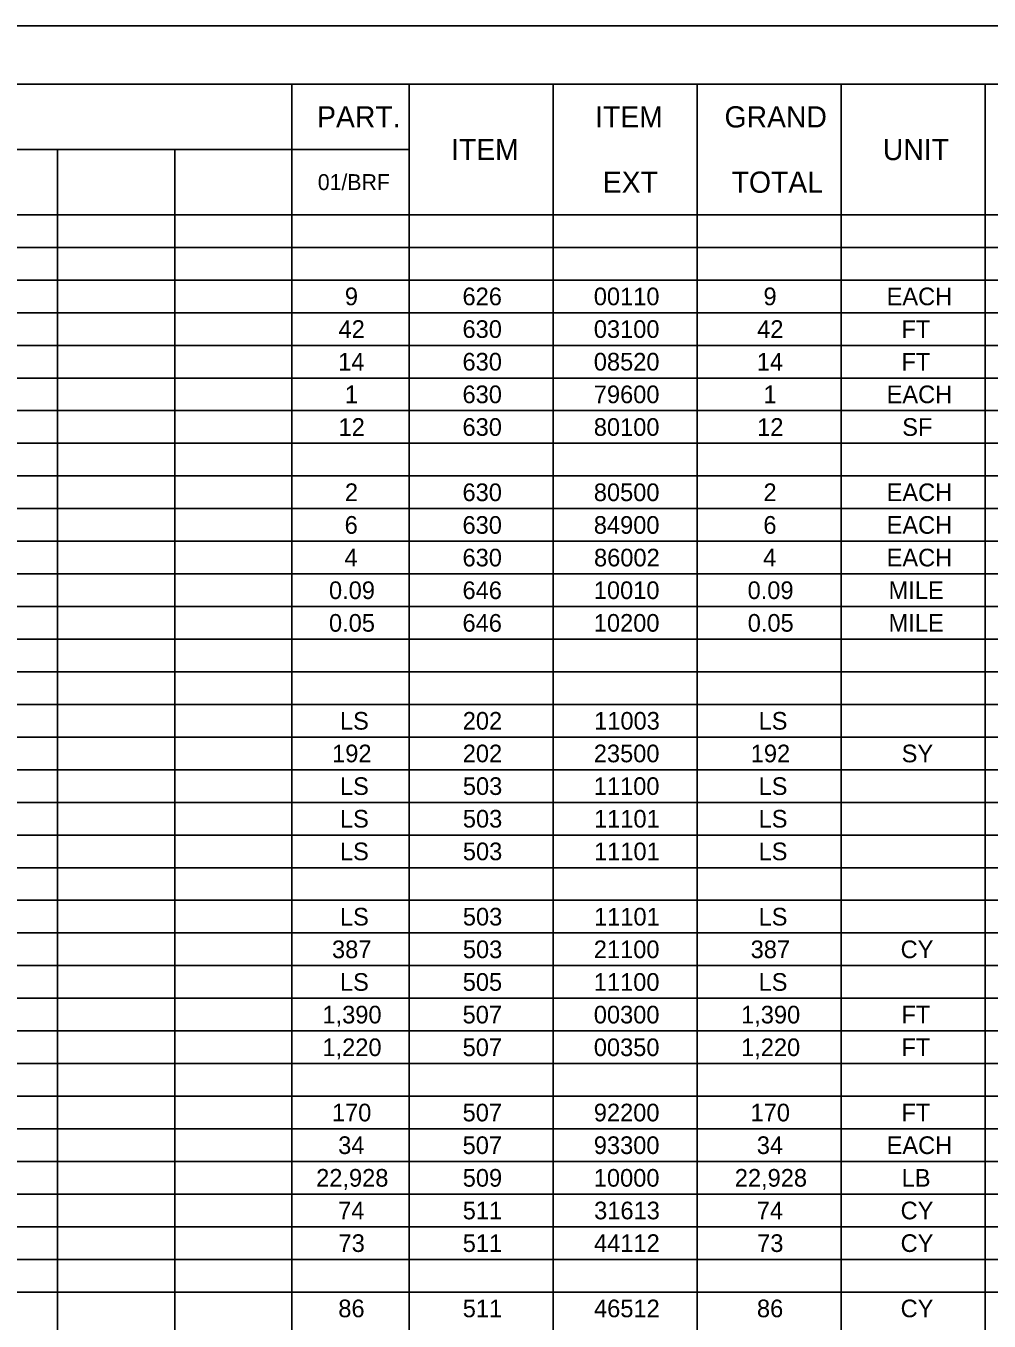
# Model space of a CAD drawing. Extents: x 0 to 34, y 0 to 22.
# Drawn here: x 8.26 to 16.52, y 10.89 to 22 of the extents above; entities that cross this region are included whole.
import ezdxf

# ---------------------------------------------------------------- set-up
doc = ezdxf.new("R2010")
doc.units = 0
for name, color, linetype in [('SH_Border', 7, 'Continuous'), ('SH_Cut_Line', 7, 'Continuous'), ('SH_Text', 7, 'Continuous')]:
    doc.layers.add(name, color=color, linetype=linetype)

msp = doc.modelspace()

# ---------------------------------------------------------------- linework, layer by layer
at = {"layer": 'SH_Border'}
msp.add_lwpolyline([(1.5, 21.5), (33.5, 21.5), (33.5, 0.5), (1.5, 0.5)], close=True, dxfattribs=at)
at = {"layer": 'SH_Cut_Line'}
msp.add_lwpolyline([(0, 0), (34, 0), (34, 22), (0, 22)], close=True, dxfattribs=at)
at = {"layer": 'SH_Text'}
for p, q in [((1.5, 21.5), (32, 21.5)), ((10.541, 21.5), (10.541, 0.5)), ((11.546, 21.5), (11.546, 0.5)), ((12.781, 21.5), (12.781, 0.5)), ((14.016, 21.5), (14.016, 0.5)), ((15.251, 21.5), (15.251, 0.5)), ((16.487, 21.5), (16.487, 0.5)), ((1.5, 20.94), (11.546, 20.94)), ((8.532, 20.94), (8.532, 0.5)), ((9.537, 20.94), (9.537, 0.5)), ((1.5, 20.38), (32, 20.38)), ((1.5, 20.1), (32, 20.1)), ((1.5, 19.82), (32, 19.82)), ((1.5, 19.54), (32, 19.54)), ((1.5, 19.26), (32, 19.26)), ((1.5, 18.98), (32, 18.98)), ((1.5, 18.7), (32, 18.7)), ((1.5, 18.42), (32, 18.42)), ((1.5, 18.14), (32, 18.14)), ((1.5, 17.86), (32, 17.86)), ((1.5, 17.58), (32, 17.58)), ((1.5, 17.3), (32, 17.3)), ((1.5, 17.02), (32, 17.02)), ((1.5, 16.74), (32, 16.74)), ((1.5, 16.46), (32, 16.46)), ((1.5, 16.18), (32, 16.18)), ((1.5, 15.9), (32, 15.9)), ((1.5, 15.62), (32, 15.62)), ((1.5, 15.34), (32, 15.34)), ((1.5, 15.06), (32, 15.06)), ((1.5, 14.78), (32, 14.78)), ((1.5, 14.5), (32, 14.5)), ((1.5, 14.22), (32, 14.22)), ((1.5, 13.94), (32, 13.94)), ((1.5, 13.66), (32, 13.66)), ((1.5, 13.38), (32, 13.38)), ((1.5, 13.1), (32, 13.1)), ((1.5, 12.82), (32, 12.82)), ((1.5, 12.54), (32, 12.54)), ((1.5, 12.26), (32, 12.26)), ((1.5, 11.98), (32, 11.98)), ((1.5, 11.7), (32, 11.7)), ((1.5, 11.42), (32, 11.42)), ((1.5, 11.14), (32, 11.14))]:
    msp.add_line(p, q, dxfattribs=at)

# ---------------------------------------------------------------- texts
for s, height, p in [('PART.', 0.1818, (10.757, 21.129)), ('ITEM', 0.1818, (13.141, 21.129)), ('GRAND', 0.1818, (14.251, 21.129)), ('ITEM', 0.1818, (11.906, 20.849)), ('UNIT', 0.1818, (15.609, 20.849)), ('01/BRF', 0.1364, (10.763, 20.592)), ('EXT', 0.1818, (13.207, 20.569)), ('TOTAL', 0.1818, (14.312, 20.569)), ('9', 0.152, (10.995, 19.604)), ('626', 0.1515, (12.004, 19.604)), ('00110', 0.1515, (13.13, 19.604)), ('9', 0.152, (14.585, 19.604)), ('EACH', 0.1515, (15.641, 19.604)), ('42', 0.1515, (10.941, 19.324)), ('630', 0.1515, (12.004, 19.324)), ('03100', 0.1515, (13.13, 19.324)), ('42', 0.1515, (14.531, 19.324)), ('FT', 0.1515, (15.768, 19.324)), ('14', 0.1515, (10.938, 19.044)), ('630', 0.1515, (12.004, 19.044)), ('08520', 0.1515, (13.13, 19.044)), ('14', 0.1515, (14.528, 19.044)), ('FT', 0.1515, (15.768, 19.044)), ('1', 0.152, (10.995, 18.764)), ('630', 0.1515, (12.004, 18.764)), ('79600', 0.1515, (13.13, 18.764)), ('1', 0.152, (14.585, 18.764)), ('EACH', 0.1515, (15.641, 18.764)), ('12', 0.1515, (10.941, 18.484)), ('630', 0.1515, (12.004, 18.484)), ('80100', 0.1515, (13.13, 18.484)), ('12', 0.1515, (14.531, 18.484)), ('SF', 0.1515, (15.775, 18.484)), ('2', 0.152, (10.995, 17.924)), ('630', 0.1515, (12.004, 17.924)), ('80500', 0.1515, (13.13, 17.924)), ('2', 0.152, (14.585, 17.924)), ('EACH', 0.1515, (15.641, 17.924)), ('6', 0.152, (10.993, 17.644)), ('630', 0.1515, (12.004, 17.644)), ('84900', 0.1515, (13.13, 17.644)), ('6', 0.152, (14.584, 17.644)), ('EACH', 0.1515, (15.641, 17.644)), ('4', 0.152, (10.992, 17.364)), ('630', 0.1515, (12.004, 17.364)), ('86002', 0.1515, (13.132, 17.364)), ('4', 0.152, (14.582, 17.364)), ('EACH', 0.1515, (15.641, 17.364)), ('0.09', 0.1515, (10.859, 17.084)), ('646', 0.1515, (12.004, 17.084)), ('10010', 0.1515, (13.13, 17.084)), ('0.09', 0.1515, (14.449, 17.084)), ('MILE', 0.1515, (15.658, 17.084)), ('0.05', 0.1515, (10.859, 16.804)), ('646', 0.1515, (12.004, 16.804)), ('10200', 0.1515, (13.13, 16.804)), ('0.05', 0.1515, (14.45, 16.804)), ('MILE', 0.1515, (15.658, 16.804)), ('LS', 0.1515, (10.953, 15.964)), ('202', 0.1515, (12.006, 15.964)), ('11003', 0.1515, (13.133, 15.964)), ('LS', 0.1515, (14.543, 15.964)), ('192', 0.1515, (10.886, 15.684)), ('202', 0.1515, (12.006, 15.684)), ('23500', 0.1515, (13.13, 15.684)), ('192', 0.1515, (14.476, 15.684)), ('SY', 0.1515, (15.77, 15.684)), ('LS', 0.1515, (10.953, 15.404)), ('503', 0.1515, (12.007, 15.404)), ('11100', 0.1515, (13.13, 15.404)), ('LS', 0.1515, (14.543, 15.404)), ('LS', 0.1515, (10.953, 15.124)), ('503', 0.1515, (12.007, 15.124)), ('11101', 0.1515, (13.132, 15.124)), ('LS', 0.1515, (14.543, 15.124)), ('LS', 0.1515, (10.953, 14.844)), ('503', 0.1515, (12.007, 14.844)), ('11101', 0.1515, (13.132, 14.844)), ('LS', 0.1515, (14.543, 14.844)), ('LS', 0.1515, (10.953, 14.284)), ('503', 0.1515, (12.007, 14.284)), ('11101', 0.1515, (13.132, 14.284)), ('LS', 0.1515, (14.543, 14.284)), ('387', 0.1515, (10.885, 14.004)), ('503', 0.1515, (12.007, 14.004)), ('21100', 0.1515, (13.13, 14.004)), ('387', 0.1515, (14.475, 14.004)), ('CY', 0.1515, (15.761, 14.004)), ('LS', 0.1515, (10.953, 13.724)), ('505', 0.1515, (12.006, 13.724)), ('11100', 0.1515, (13.13, 13.724)), ('LS', 0.1515, (14.543, 13.724)), ('1,390', 0.1515, (10.803, 13.444)), ('507', 0.1515, (12.005, 13.444)), ('00300', 0.1515, (13.13, 13.444)), ('1,390', 0.1515, (14.393, 13.444)), ('FT', 0.1515, (15.768, 13.444)), ('1,220', 0.1515, (10.803, 13.164)), ('507', 0.1515, (12.005, 13.164)), ('00350', 0.1515, (13.13, 13.164)), ('1,220', 0.1515, (14.393, 13.164)), ('FT', 0.1515, (15.768, 13.164)), ('170', 0.1515, (10.884, 12.604)), ('507', 0.1515, (12.005, 12.604)), ('92200', 0.1515, (13.13, 12.604)), ('170', 0.1515, (14.474, 12.604)), ('FT', 0.1515, (15.768, 12.604)), ('34', 0.1515, (10.938, 12.324)), ('507', 0.1515, (12.005, 12.324)), ('93300', 0.1515, (13.13, 12.324)), ('34', 0.1515, (14.528, 12.324)), ('EACH', 0.1515, (15.641, 12.324)), ('22,928', 0.1515, (10.749, 12.044)), ('509', 0.1515, (12.006, 12.044)), ('10000', 0.1515, (13.13, 12.044)), ('22,928', 0.1515, (14.339, 12.044)), ('LB', 0.1515, (15.77, 12.044)), ('74', 0.1515, (10.938, 11.764)), ('511', 0.1515, (12.006, 11.764)), ('31613', 0.1515, (13.133, 11.764)), ('74', 0.1515, (14.528, 11.764)), ('CY', 0.1515, (15.761, 11.764)), ('73', 0.1515, (10.941, 11.484)), ('511', 0.1515, (12.006, 11.484)), ('44112', 0.1515, (13.132, 11.484)), ('73', 0.1515, (14.531, 11.484)), ('CY', 0.1515, (15.761, 11.484)), ('86', 0.1515, (10.939, 10.924)), ('511', 0.1515, (12.006, 10.924)), ('46512', 0.1515, (13.132, 10.924)), ('86', 0.1515, (14.529, 10.924)), ('CY', 0.1515, (15.761, 10.924))]:
    msp.add_text(s, height=height, dxfattribs=at).set_placement(p)

doc.saveas('drawing.dxf')
